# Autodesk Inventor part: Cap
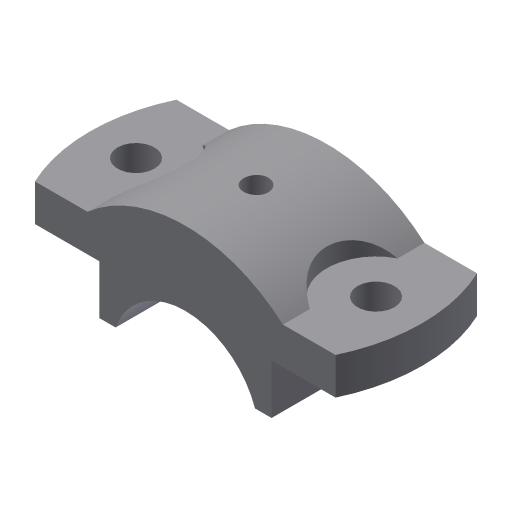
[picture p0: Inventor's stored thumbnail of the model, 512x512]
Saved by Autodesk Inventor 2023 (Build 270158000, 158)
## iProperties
Created: 2009-04
Part Number: Cap
Document SubType Name: Modeling
Designer: Sham
Density: 1 g/cm^3
Material: Generic
Appearance: Default
Author: Sham
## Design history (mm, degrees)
sketch "Sketch1"
  geometry: L1 (-48.857, 23)-(48.857, 23); L2 (48.857, -23)-(-48.857, -23); A1 r 54 centre (0, 0) between (-48.857, 23) and (-48.857, -23); A2 r 54 centre (0, 0) between (48.857, -23) and (48.857, 23); 1 further point
  constraints: 4 end point, 4 point on circle, 2 centre point, 2 coincident, 1 horizontal, 1 parallel, 1 other
  dimensions: "d3" = 54 radius of A1; "d4" = 54 radius of A2; "d5" = 46 distance between parallel lines of L2 L1; "d6" = 23 distance from line of point (0, 0) L1
extrude "Extrusion1" new body sketch "Sketch1" distance "d7" = 12; taper "d8" = 0 deg
sketch "Sketch3"
  geometry: L1 (20.906, 0)-(20.906, -16); L2 (76.906, -0.137)-(76.906, -16.137); L3 (20.906, -16)-(26.23, -16); L4 (71.532, -16.137)-(76.906, -16.137); L5 (76.906, -0.137)-(76.857, 12); L6 (97.714, 0)-(0, 0) reference; L7 (76.857, 12)-(80.606, 12); L8 (17.108, 12)-(20.906, 12); L9 (20.906, 12)-(20.906, 0); L10 (0, 12)-(97.714, 12) reference; A1 r 24 centre (48.857, -24) between (71.532, -16.137) and (26.23, -16); A2 r 48 centre (48.857, -24) between (80.606, 12) and (17.108, 12); 3 further points
  constraints: 16 end point, 4 point on circle, 3 parallel, 3 perpendicular, 2 centre point, 2 coincident, 2 vertical alignment, 1 collinear, 1 midpoint, 1 vertical, 2 other
  dimensions: "d17" = 48 diameter of A1; "d18" = 16 distance of L1.start L1.end; "d19" = 56 distance between parallel lines of L2 L1; "d21" = 8 vertical distance of A1.centre L1.end; "d22" = 48 radius of A2; "d23" = 0 distance from line of L6 L1.start; "d38" = 31.74902 distance of L7.end point (48.857, 12); "d39" = 28 distance from line of point (48.857, 12) L5
extrude "Extrusion2" join sketch "Sketch3" stored distance "d24" = 12; taper "d25" = 0 deg
sketch "Sketch4"
  geometry: 2 further points
  dimensions: "d26" = 78 distance of point (39, 0) point (-39, 0)
hole "Hole1" sketch "Sketch4" at (-39, 0), (39, 0) diameter "d28" = 12; stored, may be unused: countersink angle "d32" = 90 deg, drill point angle "d34" = 118 deg; dims "d29" = 6, "d30" = 4, "d31" = 2, "d33" = 8
sketch "Sketch5"
  geometry: L1 (-31.749, -23)-(-31.749, 23) reference; L2 (-31.749, 14.263)-(-31.749, -14.263); C1 r 6 at (-39, 0) reference; A1 r 16 centre (-39, 0) between (-31.749, -14.263) and (-31.749, 14.263)
  constraints: 2 end point, 2 point on circle, 1 centre point, 1 coincident, 1 collinear, 1 point on line
  dimensions: "d35" = 16 radius of A1
extrude "Extrusion3" cut sketch "Sketch5" distance "d36" = 12; taper "d37" = 0 deg
mirror "Mirror2"
workplane "Work Plane4"
sketch "Sketch6"
  geometry: L1 (-31.749, 0)-(31.749, 0) reference; 1 further point
  dimensions: "d40" = 23 distance from line of L1 point (0, 23)
hole "Hole2" sketch "Sketch6" at (0, 23) diameter "d41" = 6; stored, may be unused: countersink angle "d45" = 90 deg, drill point angle "d47" = 118 deg; dims "d42" = 6, "d43" = 8, "d44" = 16, "d46" = 8
body "Solid1"
